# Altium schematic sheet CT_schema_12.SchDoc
size 742 x 377 mm
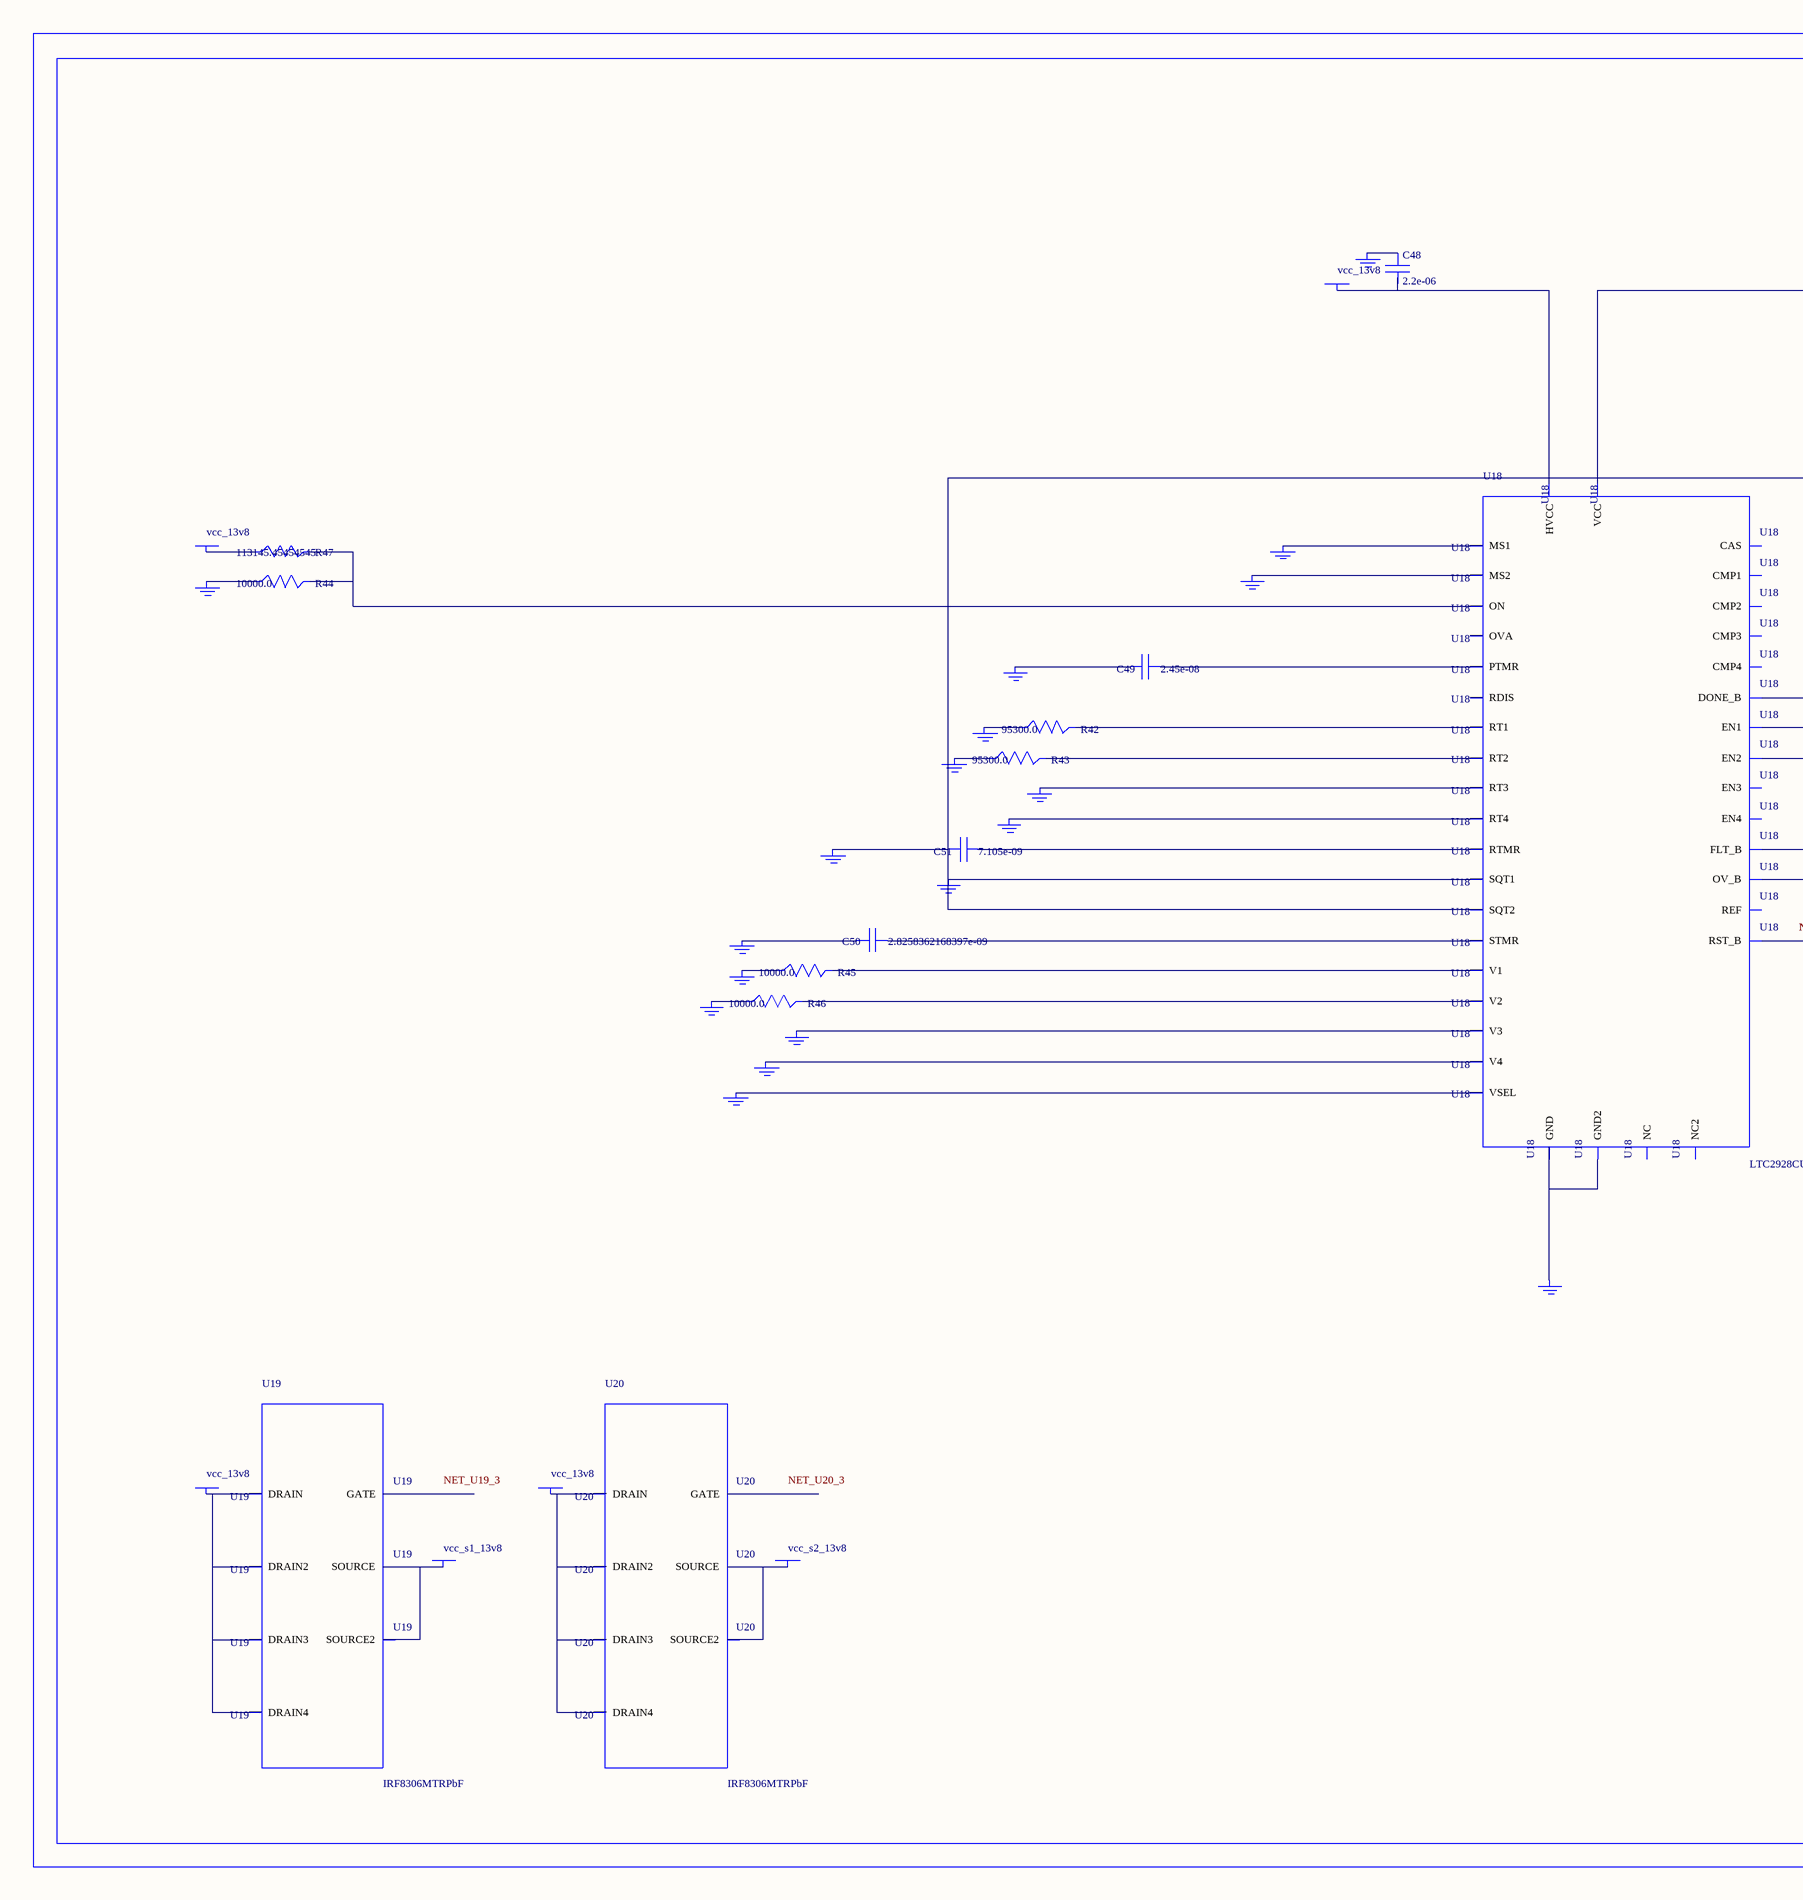
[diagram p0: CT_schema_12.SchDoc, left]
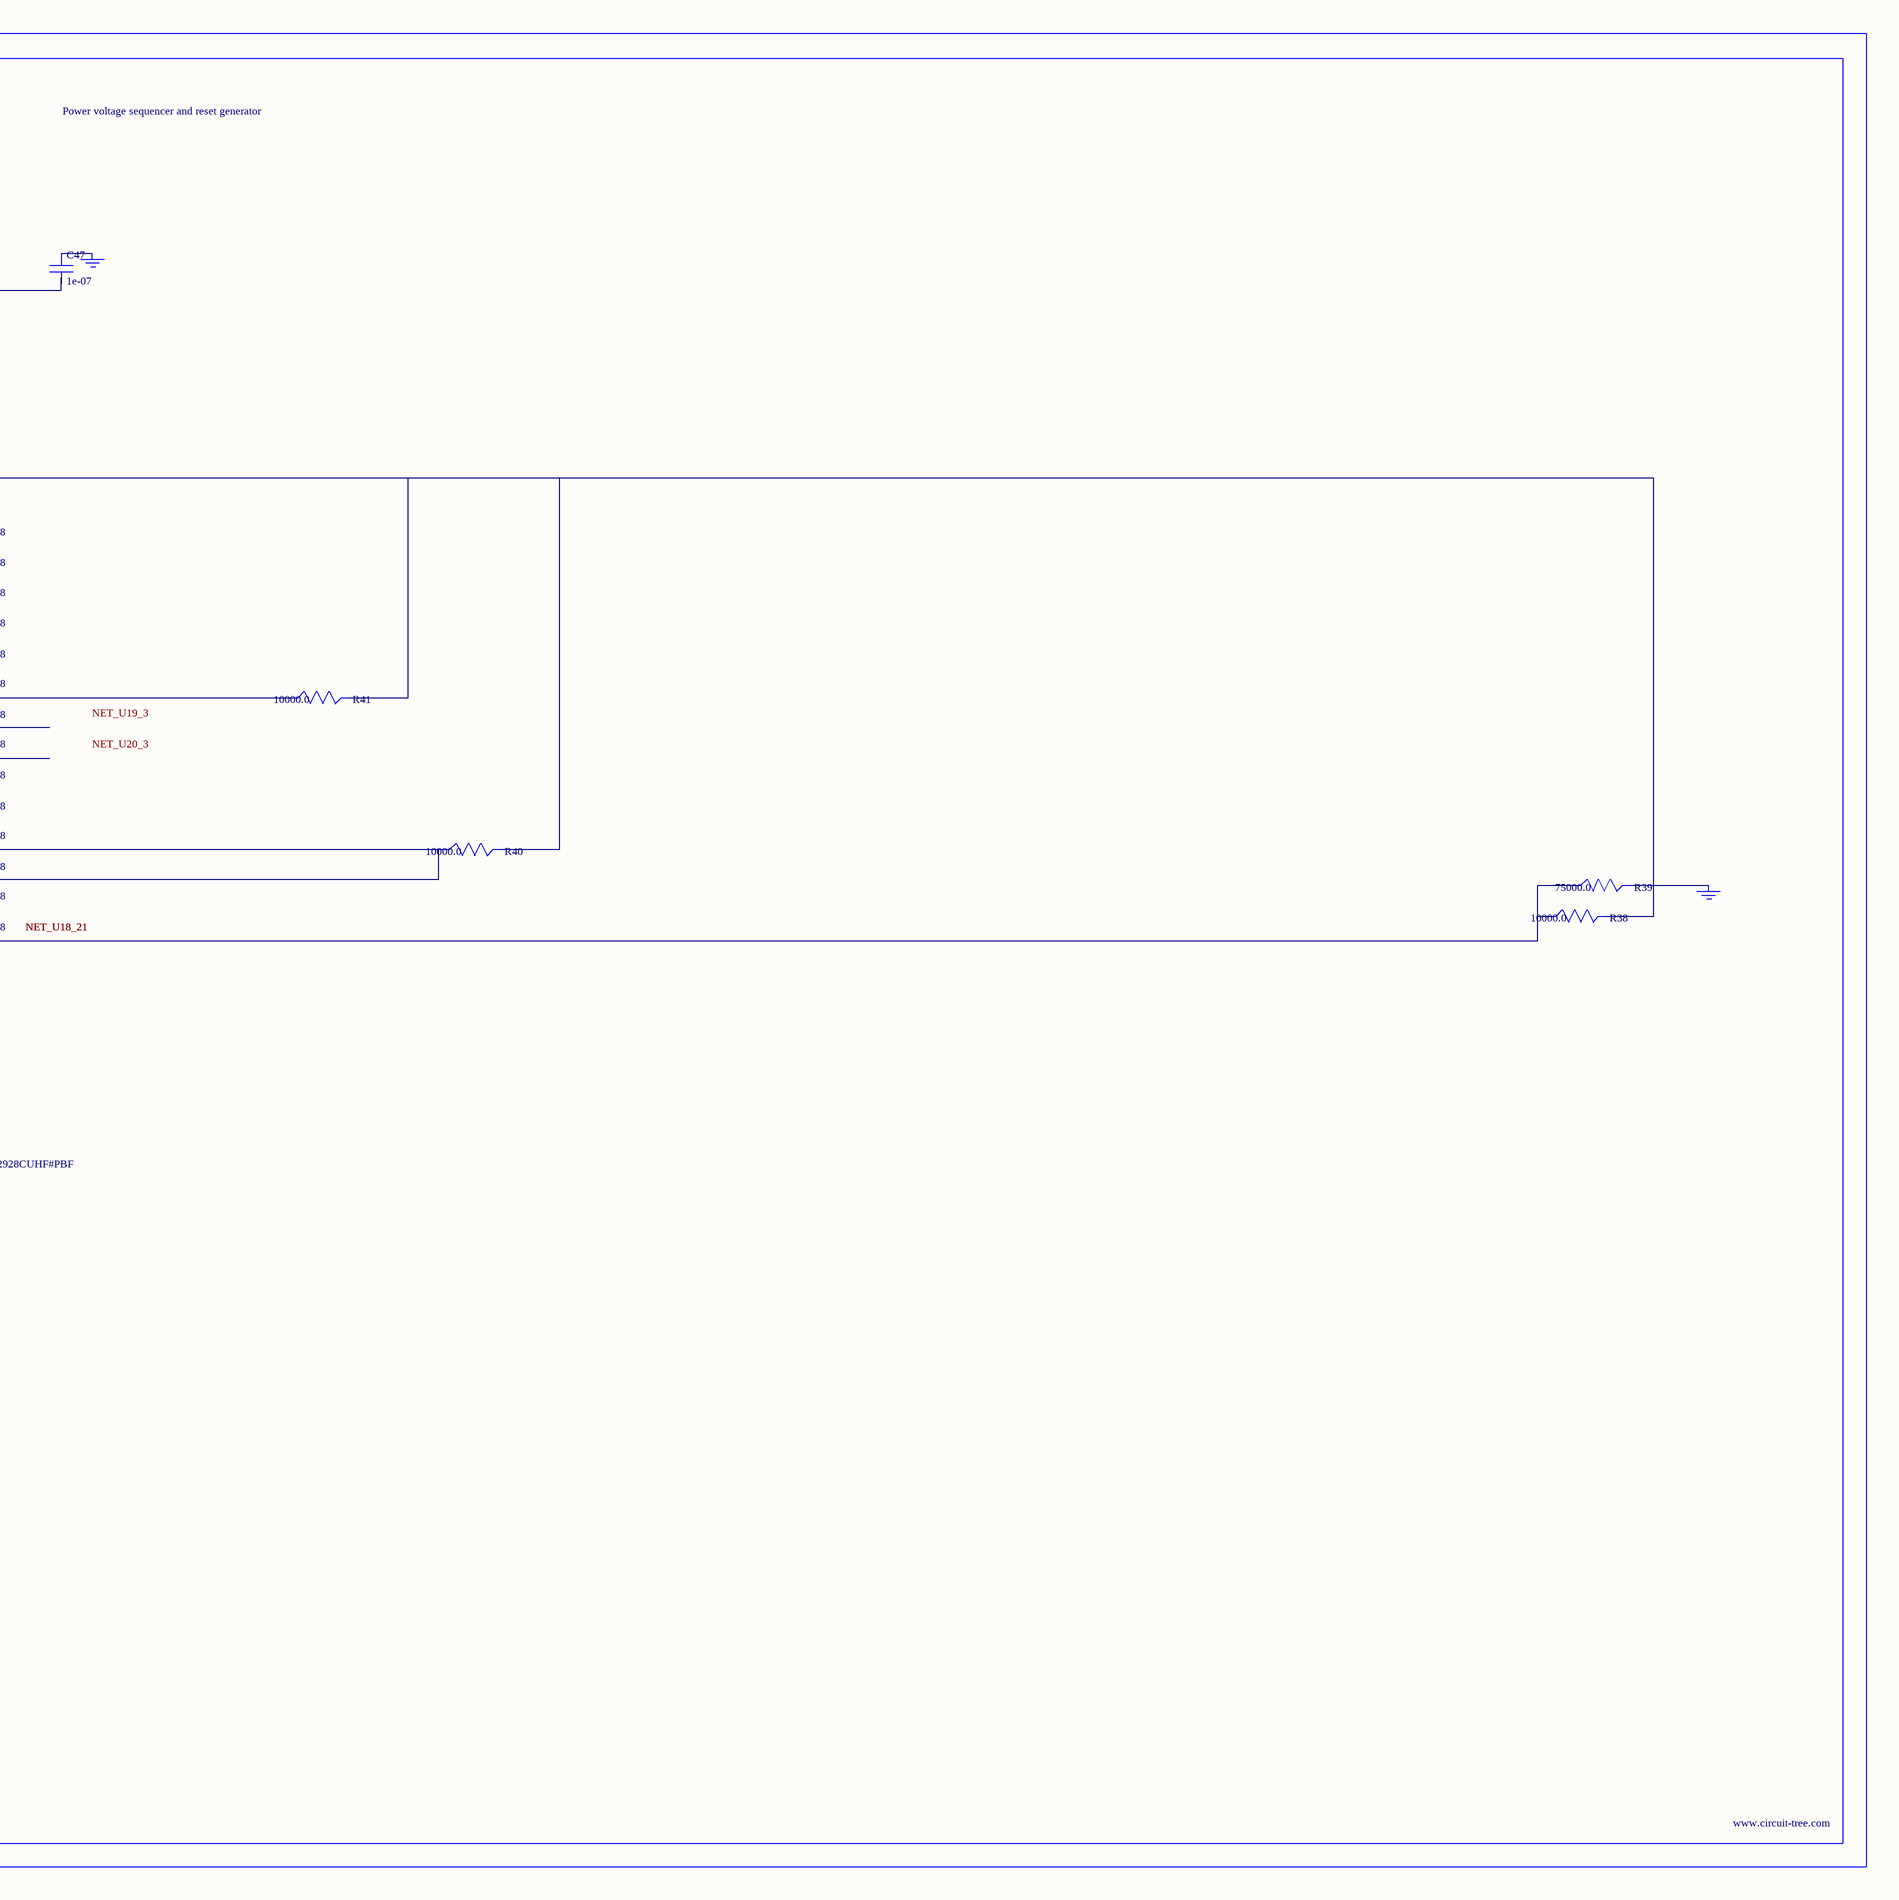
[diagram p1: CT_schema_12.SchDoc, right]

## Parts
BORDER11  (no value)
C47  1e-07  [C0402]
C48  2.2e-06  [C0603]
C49  2.45e-08  [R0603]
C50  2.8258362168397e-09  [R0603]
C51  7.105e-09  [R0603]
GND_INSTANCE_11_0  (no value)
GND_INSTANCE_11_1  (no value)
GND_INSTANCE_11_2  (no value)
GND_INSTANCE_11_3  (no value)
GND_INSTANCE_11_4  (no value)
GND_INSTANCE_11_5  (no value)
GND_INSTANCE_11_6  (no value)
GND_INSTANCE_11_7  (no value)
GND_INSTANCE_11_8  (no value)
GND_INSTANCE_11_9  (no value)
GND_INSTANCE_11_10  (no value)
GND_INSTANCE_11_11  (no value)
GND_INSTANCE_11_12  (no value)
GND_INSTANCE_11_13  (no value)
GND_INSTANCE_11_14  (no value)
GND_INSTANCE_11_15  (no value)
GND_INSTANCE_11_16  (no value)
GND_INSTANCE_11_17  (no value)
GND_INSTANCE_11_18  (no value)
GND_INSTANCE_11_19  (no value)
POWER_INSTANCE_11_0  vcc_13v8
POWER_INSTANCE_11_1  vcc_13v8
POWER_INSTANCE_11_2  vcc_13v8
POWER_INSTANCE_11_3  vcc_s1_13v8
POWER_INSTANCE_11_4  vcc_13v8
POWER_INSTANCE_11_5  vcc_s2_13v8
R38  10000.0  [R0603]
R39  75000.0  [R0603]
R40  10000.0  [R0603]
R41  10000.0  [R0603]
R42  95300.0  [R0603]
R43  95300.0  [R0603]
R44  10000.0  [R0603]
R45  10000.0  [R0603]
R46  10000.0  [R0603]
R47  113145.45454545  [R0603]
U18  LTC2928CUHF#PBF  [QFN-38_UHF]
U19  IRF8306MTRPbF  [IRF8306MTRPBF]
U20  IRF8306MTRPbF  [IRF8306MTRPBF]

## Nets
NetC47_1: C47.1 GND_INSTANCE_11_10.0(GND)
NetC47_2: C47.2 C51.2 GND_INSTANCE_11_5.0(GND) GND_INSTANCE_11_15.0(GND) R38.2 R40.2 R41.2 U18.10(SQT1) U18.11(SQT2) U18.22(VCC)
NetC48_1: C48.1 GND_INSTANCE_11_11.0(GND)
NetC48_2: C48.2 POWER_INSTANCE_11_1.0(PWR) U18.23(HVCC)
NetC49_1: C49.1 U18.27(PTMR)
NetC49_2: C49.2 GND_INSTANCE_11_14.0(GND)
NetC50_1: C50.1 U18.26(STMR)
NetC50_2: C50.2 GND_INSTANCE_11_13.0(GND)
NetC51_1: C51.1 U18.28(RTMR)
NetGND_INSTANCE_11_0_0: GND_INSTANCE_11_0.0(GND) R45.1
NetGND_INSTANCE_11_1_0: GND_INSTANCE_11_1.0(GND) R42.1
NetGND_INSTANCE_11_2_0: GND_INSTANCE_11_2.0(GND) R43.1
NetGND_INSTANCE_11_3_0: GND_INSTANCE_11_3.0(GND) U18.8(RT3)
NetGND_INSTANCE_11_4_0: GND_INSTANCE_11_4.0(GND) U18.9(RT4)
NetGND_INSTANCE_11_6_0: GND_INSTANCE_11_6.0(GND) U18.12(MS1)
NetGND_INSTANCE_11_7_0: GND_INSTANCE_11_7.0(GND) U18.13(MS2)
NetGND_INSTANCE_11_8_0: GND_INSTANCE_11_8.0(GND) R44.1
NetGND_INSTANCE_11_9_0: GND_INSTANCE_11_9.0(GND) R39.2
NetGND_INSTANCE_11_12_0: GND_INSTANCE_11_12.0(GND) U18.25(VSEL)
NetGND_INSTANCE_11_16_0: GND_INSTANCE_11_16.0(GND) U18.30(V4)
NetGND_INSTANCE_11_17_0: GND_INSTANCE_11_17.0(GND) U18.32(V3)
NetGND_INSTANCE_11_18_0: GND_INSTANCE_11_18.0(GND) R46.1
NetGND_INSTANCE_11_19_0: GND_INSTANCE_11_19.0(GND) U18.24(GND) U18.39(GND2)
NetPOWER_INSTANCE_11_0_0: POWER_INSTANCE_11_0.0(PWR) R47.1
NetPOWER_INSTANCE_11_2_0: POWER_INSTANCE_11_2.0(PWR) U19.1(DRAIN) U19.2(DRAIN2) U19.6(DRAIN3) U19.7(DRAIN4)
NetPOWER_INSTANCE_11_3_0: POWER_INSTANCE_11_3.0(PWR) U19.4(SOURCE) U19.5(SOURCE2)
NetPOWER_INSTANCE_11_4_0: POWER_INSTANCE_11_4.0(PWR) U20.1(DRAIN) U20.2(DRAIN2) U20.6(DRAIN3) U20.7(DRAIN4)
NetPOWER_INSTANCE_11_5_0: POWER_INSTANCE_11_5.0(PWR) U20.4(SOURCE) U20.5(SOURCE2)
NetR38_1: R38.1 R39.1 U18.21(RST_B)
NetR40_1: R40.1 U18.19(FLT_B) U18.20(OV_B)
NetR41_1: R41.1 U18.18(DONE_B)
NetR42_2: R42.2 U18.6(RT1)
NetR43_2: R43.2 U18.7(RT2)
NetR44_2: R44.2 R47.2 U18.16(ON)
NetR45_2: R45.2 U18.3(V1)
NetR46_2: R46.2 U18.38(V2)

Not connected (* = marked no-connect by the designer): U18 1(OVA) 2(EN1) 4(NC) 5(REF) 14(RDIS) 15(CAS) 17(NC2) 29(EN4) 31(EN3) 33(CMP3) 34(CMP4) 35(CMP1) 36(CMP2) 37(EN2); U19 3(GATE); U20 3(GATE)

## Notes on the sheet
- Labels drawn without touching a wire or pin: NET_U19_3, NET_U20_3

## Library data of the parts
BORDER11 = BORDER_PAGE11
C47 = C0402C104K3RACTU
C48 = GRM188R61H225KE1115D
C49 = C49
C50 = C50
C51 = C51
GND_INSTANCE_11_0-GND_INSTANCE_11_19 = GND
POWER_INSTANCE_11_0-POWER_INSTANCE_11_5 = PWR
R38 R40 R41 R44-R46 = RC0603JR-0710KL
R39 = RC0603JR-0775KL
R42 R43 = RC0603FR-0795K3L
R47 = R47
